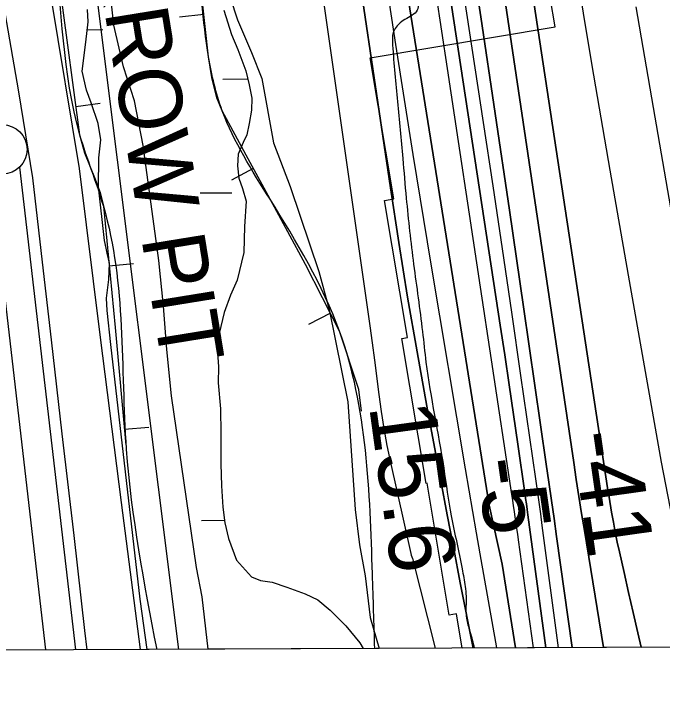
# Model space of a CAD drawing. Extents: x 3419139 to 3457078, y 540382 to 565875.
# Drawn here: x 3437926 to 3438584, y 545772 to 546482 of the extents above; entities that cross this region are included whole.
import ezdxf

# ---------------------------------------------------------------- set-up
doc = ezdxf.new("R2010")
doc.units = 0
for name, color, linetype in [('V-BORW-IDEN', 7, 'Continuous'), ('V-BORW-LINE', 7, 'Continuous'), ('V-FLOD-BASE', 7, 'Continuous'), ('V-GRID-FRAM', 7, 'Continuous'), ('V-LEVE-TOET', 7, 'Continuous'), ('V-RIVR-EDGE', 7, 'Continuous'), ('V-RIVR-RANG', 7, 'Continuous'), ('V-RRAP-RVMT', 7, 'Continuous'), ('V-SITE-VEGE', 7, 'Continuous'), ('V-SURV-LINE', 7, 'Continuous'), ('V-TOPO-DPTH', 7, 'Continuous'), ('V-TOPO-MAJR', 7, 'Continuous'), ('V-TOPO-MINR', 7, 'Continuous'), ('V-TOPO-SHOR', 7, 'Continuous'), ('V-TOPO-WATR', 7, 'Continuous'), ('V-WETL-SWMP', 7, 'Continuous')]:
    doc.layers.add(name, color=color, linetype=linetype)

msp = doc.modelspace()

# ---------------------------------------------------------------- linework, layer by layer
at = {"layer": 'V-BORW-LINE'}
for p, q in [((3438118.89, 546481.53), (3438094.04, 546478.85)), ((3437988.83, 546388.05), (3438013.6, 546391.42)), ((3438168.96, 546325.09), (3438147, 546313.15)), ((3438022.64, 546226.05), (3438047.52, 546228.45)), ((3438247.2, 546178.02), (3438224.94, 546166.63)), ((3438038.21, 546060.18), (3438063.1, 546062.48))]:
    msp.add_line(p, q, dxfattribs=at)
for points in [[(3437942.25, 546712.52), (3437948.67, 546671.17), (3437967.01, 546551.57), (3437979.67, 546455.42), (3437992.74, 546359.28), (3437997.56, 546340.87), (3438008.53, 546314.14), (3438013.51, 546300.66), (3438016.78, 546286.78), (3438028.67, 546163.44), (3438039.69, 546044.1)], [(3438278.93, 546078.47), (3438276.06, 546100.66), (3438256.5, 546159.84), (3438221.81, 546227.61), (3438185.94, 546293.87), (3438161.59, 546338.64), (3438137.5, 546383.7), (3438132.03, 546396.74), (3438126.84, 546417.38), (3438123.54, 546438.47), (3438117.54, 546494.06), (3438111.24, 546549.53), (3438101.67, 546602.31), (3438092.02, 546655.07)]]:
    msp.add_lwpolyline(points, dxfattribs=at)
for points in [[(3438092.02, 546655.07), (3438072.18, 546746.33), (3438070.57, 546844.66), (3438043.73, 546925.07), (3437954.19, 546899.65), (3437930.11, 546790.72), (3437967.01, 546551.57), (3437992.74, 546359.28), (3438016.78, 546286.78), (3438040.07, 546040.04), (3438070.94, 545836.65)], [(3438292.3, 545837.61), (3438289.94, 545913.29), (3438256.5, 546159.84), (3438185.94, 546293.87), (3438137.5, 546383.7), (3438123.54, 546438.47), (3438111.24, 546549.53), (3438092.02, 546655.07)]]:
    msp.add_spline(points, degree=3, dxfattribs=at)
at = {"layer": 'V-FLOD-BASE'}
msp.add_lwpolyline([(3437916.8, 546483.16), (3437930.62, 546402.92), (3437944.81, 546315.45), (3437955.68, 546221.11), (3437963.73, 546150.91), (3437974.68, 546055.66), (3437986.81, 545952.37), (3437997.5, 545855.97), (3438000.14, 545836.34)], dxfattribs=at)
at = {"layer": 'V-GRID-FRAM'}
msp.add_lwpolyline([(3423200.92, 563955.08), (3454837.93, 564093.12), (3454925.21, 545910.19), (3423272.32, 545772.07), (3423200.92, 563955.08)], dxfattribs=at)
at = {"layer": 'V-LEVE-TOET'}
msp.add_lwpolyline([(3437963.61, 546499.37), (3437992.25, 546324.92), (3438013.64, 546153.59), (3438034.77, 545986.02), (3438054.19, 545836.58)], dxfattribs=at)
at = {"layer": 'V-RIVR-EDGE'}
msp.add_spline([(3438029.6, 548401.43), (3438045.73, 548402.06), (3438053.4, 548398.75), (3438061.79, 548390.32), (3438061.77, 548385.2), (3438061.75, 548375.7), (3438057.34, 548366.21), (3438052.93, 548358.17), (3438050.73, 548351.97), (3438051.06, 548340.63), (3438052.5, 548331.86), (3438054.32, 548327.47), (3438053.57, 548319.42), (3438050.98, 548307.73), (3438050.59, 548295.31), (3438050.56, 548286.17), (3438052.7, 548262.77), (3438054.46, 548237.91), (3438056.96, 548212.31), (3438063.86, 548193.29), (3438064.89, 548167.69), (3438067.34, 548123.09), (3438069.47, 548097.13), (3438073.45, 548080.67), (3438079.99, 548063.84), (3438085.82, 548055.05), (3438092.37, 548044.07), (3438096.37, 548034.56), (3438099.99, 548022.48), (3438101.78, 548005.66), (3438104.97, 547964.72), (3438108.52, 547922.3), (3438110.26, 547886.47), (3438114.23, 547867.46), (3438119.66, 547845.88), (3438125.12, 547835.26), (3438137.83, 547801.23), (3438150.88, 547759.89), (3438154.82, 547724.79), (3438158.04, 547698.46), (3438169.17, 547616.55), (3438172.41, 547594.25), (3438175.3, 547583.27), (3438178.2, 547571.93), (3438178.18, 547561.33), (3438178.15, 547552.56), (3438179.97, 547548.9), (3438186.55, 547549.25), (3438192.03, 547546.31), (3438193.11, 547541.19), (3438193.1, 547535.71), (3438190.9, 547531.33), (3438186.13, 547526.95), (3438185.75, 547521.84), (3438187.21, 547518.18), (3438190.12, 547513.05), (3438190.1, 547507.2), (3438190.09, 547500.62), (3438190.08, 547497.7), (3438185.31, 547491.5), (3438184.57, 547485.65), (3438186.01, 547476.51), (3438194.33, 547443.95), (3438199.03, 547422.74), (3438199, 547408.12), (3438201.16, 547394.22), (3438204.04, 547375.57), (3438203.99, 547358.76), (3438204.3, 547334.26), (3438206.07, 547310.13), (3438210.73, 547274.66), (3438218.3, 547230.05), (3438220.47, 547219.81), (3438225.94, 547215.77), (3438232.52, 547215.76), (3438232.87, 547211.37), (3438229.94, 547206.62), (3438229.92, 547198.95), (3438232.46, 547191.63), (3438235.37, 547186.14), (3438235.36, 547182.48), (3438234.97, 547173.35), (3438233.5, 547167.5), (3438230.2, 547164.22), (3438223.61, 547162.04), (3438223.97, 547157.29), (3438226.15, 547152.17), (3438229.07, 547150.33), (3438234.92, 547151.41), (3438243.69, 547152.85), (3438248.44, 547149.19), (3438249.88, 547140.04), (3438251.3, 547125.78), (3438250.55, 547117.01), (3438245.78, 547109.71), (3438239.19, 547106.81), (3438225.66, 547102.09), (3438222.36, 547099.17), (3438219.42, 547093.7), (3438217.2, 547082.73), (3438216.8, 547067.75), (3438218.96, 547055.68), (3438228.8, 547041.03), (3438234.26, 547034.81), (3438234.24, 547026.76), (3438234.23, 547019.82), (3438234.58, 547013.97), (3438237.12, 547005.55), (3438239.28, 546994.58), (3438242.56, 546990.92), (3438247.68, 546989.44), (3438253.51, 546981.75), (3438257.5, 546969.31), (3438259.67, 546959.44), (3438258.9, 546944.09), (3438254.86, 546937.52), (3438253.38, 546932.04), (3438253.37, 546924.73), (3438259.2, 546918.86), (3438262.47, 546912.28), (3438266.09, 546895.82), (3438272.63, 546878.99), (3438274.42, 546864.73), (3438272.92, 546851.2), (3438272.17, 546840.24), (3438274.72, 546839.87), (3438276.2, 546844.25), (3438280.23, 546850.45), (3438283.52, 546849.72), (3438283.88, 546845.33), (3438283.85, 546832.9), (3438282.36, 546823.4), (3438276.86, 546817.56), (3438271, 546811.36), (3438270.99, 546807.71), (3438272.79, 546798.57), (3438280.81, 546788.31), (3438282.27, 546788.67), (3438287.77, 546791.95), (3438291.78, 546790.11), (3438292.5, 546784.26), (3438292.13, 546781.34), (3438288.46, 546778.79), (3438285.53, 546773.68), (3438283.32, 546766.74), (3438282.92, 546755.41), (3438281.8, 546746.64), (3438286.87, 546723.96), (3438290.44, 546690.68), (3438295.81, 546645.34), (3438301.55, 546600), (3438307.65, 546556.49), (3438313.8, 546530.88), (3438318.89, 546519.54), (3438322.18, 546516.97), (3438327.66, 546516.96), (3438334.96, 546511.09), (3438335.65, 546496.47), (3438336, 546487.33), (3438324.64, 546477.49), (3438318.05, 546473.12), (3438311.08, 546463.26), (3438310.32, 546450.47), (3438315.29, 546393.07), (3438320.63, 546335.3), (3438324.19, 546295.08), (3438331.7, 546227.8), (3438340.67, 546159.42), (3438344.25, 546128.34), (3438362.26, 546020.82), (3438369.81, 545972.19), (3438381.01, 545918.42), (3438383.89, 545900.5), (3438384.97, 545890.63), (3438384.95, 545884.42), (3438385.28, 545868.33), (3438388.9, 545854.8), (3438393.3, 545838.05)], degree=3, dxfattribs=at)
at = {"layer": 'V-RRAP-RVMT'}
for p, q in [((3438475.22, 546468.82), (3438451.09, 546613.22)), ((3438287.6, 546437.47), (3438475.22, 546468.82)), ((3438311.45, 546294.18), (3438287.6, 546437.47)), ((3438302.11, 546292.65), (3438311.45, 546294.18)), ((3438325.37, 546153.31), (3438302.11, 546292.65)), ((3438319.77, 546152.4), (3438325.37, 546153.31)), ((3438344.37, 546005.18), (3438319.77, 546152.4)), ((3438345.57, 546005.37), (3438344.37, 546005.18)), ((3438367.93, 545871.53), (3438345.57, 546005.37)), ((3438375.24, 545872.72), (3438367.93, 545871.53)), ((3438381.03, 545838), (3438375.24, 545872.72)), ((3438730.73, 545839.53), (3438381.03, 545838))]:
    msp.add_line(p, q, dxfattribs=at)
at = {"layer": 'V-SITE-VEGE'}
for p, q in [((3438027.33, 546470.7), (3438023.42, 546508.36)), ((3438144.7, 546501.48), (3438152.97, 546476.18)), ((3438152.97, 546476.18), (3438167.04, 546442.93)), ((3438037.4, 546428.38), (3438027.33, 546470.7)), ((3438167.04, 546442.93), (3438177.72, 546416.41)), ((3438048.37, 546393.77), (3438037.4, 546428.38)), ((3438177.72, 546416.41), (3438189.55, 546351.04)), ((3438057.04, 546348.53), (3438048.37, 546393.77)), ((3438073.22, 546231.76), (3438057.04, 546348.53)), ((3438189.55, 546351.04), (3438206.31, 546306.61)), ((3438206.31, 546306.61), (3438216.45, 546276.65)), ((3438216.45, 546276.65), (3438235.54, 546220.53)), ((3438077.77, 546185.16), (3438073.22, 546231.76)), ((3438235.54, 546220.53), (3438245.81, 546181.8)), ((3438081.3, 546141.32), (3438077.77, 546185.16)), ((3438245.81, 546181.8), (3438264.86, 546088.04)), ((3438086.01, 546094.04), (3438081.3, 546141.32)), ((3438111.31, 545919.82), (3438086.01, 546094.04)), ((3438264.86, 546088.04), (3438272.32, 545978.71)), ((3438272.32, 545978.71), (3438276.75, 545942.94)), ((3438276.75, 545942.94), (3438282.59, 545911.46)), ((3438116.98, 545890.06), (3438111.31, 545919.82)), ((3438282.59, 545911.46), (3438287.5, 545869.16)), ((3438123.02, 545836.88), (3438116.98, 545890.06)), ((3438287.5, 545869.16), (3438296.67, 545837.63)), ((3438296.67, 545837.63), (3438123.02, 545836.88))]:
    msp.add_line(p, q, dxfattribs=at)
at = {"layer": 'V-SURV-LINE'}
for points in [[(3437958.31, 545836.16), (3437901.77, 546322.87)], [(3437931.57, 546326.35), (3437988.49, 545836.29)]]:
    msp.add_lwpolyline(points, dxfattribs=at)
msp.add_circle((3437914.36, 546344.46), 25, dxfattribs=at)
at = {"layer": 'V-TOPO-DPTH'}
for points in [[(3437991.54, 548933.35), (3438051.83, 548524.53), (3438060.22, 548473.42), (3438165.61, 547710.29), (3438237.41, 547136.26), (3438265.79, 546904.61), (3438321.05, 546529.85), (3438408.25, 545983.03), (3438421.72, 545923.4), (3438435.06, 545838.24)], [(3437991.54, 548933.35), (3438051.83, 548524.53), (3438060.22, 548473.42), (3438165.61, 547710.29), (3438237.41, 547136.26), (3438265.79, 546904.61), (3438321.05, 546529.85), (3438408.25, 545983.03), (3438421.72, 545923.4), (3438435.06, 545838.24)], [(3438243.53, 547691.29), (3438244.92, 547681.67), (3438246.33, 547672.05), (3438247.76, 547662.43), (3438249.21, 547652.81), (3438357, 546943.52), (3438359.01, 546930.3), (3438361.02, 546917.08), (3438363.04, 546903.86), (3438365.05, 546890.64), (3438380.95, 546786.36), (3438390.87, 546720.99), (3438400.74, 546655.62), (3438410.53, 546590.24), (3438420.27, 546524.84), (3438494.14, 546026.61), (3438496.76, 546009.27), (3438499.42, 545991.94), (3438502.17, 545974.61), (3438504.97, 545957.3), (3438524.44, 545838.63)], [(3438524.44, 545838.63), (3438504.97, 545957.3), (3438502.17, 545974.61), (3438499.42, 545991.94), (3438496.76, 546009.27), (3438494.14, 546026.61), (3438420.27, 546524.84), (3438410.53, 546590.24), (3438400.74, 546655.62), (3438390.87, 546720.99), (3438380.95, 546786.36), (3438365.05, 546890.64), (3438363.04, 546903.86), (3438361.02, 546917.08), (3438359.01, 546930.3), (3438357, 546943.52), (3438249.21, 547652.81), (3438247.76, 547662.43), (3438246.33, 547672.05), (3438244.92, 547681.67), (3438243.53, 547691.29)], [(3438220.75, 547679.15), (3438239.4, 547547.91), (3438250.77, 547468.62), (3438262.28, 547389.35), (3438274, 547310.11), (3438285.84, 547230.89), (3438325.78, 546966.16), (3438329.83, 546939.32), (3438333.89, 546912.49), (3438337.96, 546885.66), (3438342.04, 546858.83), (3438384.92, 546577.27), (3438399.75, 546479.12), (3438414.44, 546380.95), (3438428.91, 546282.75), (3438443.23, 546184.53), (3438466.36, 546024.71), (3438469, 546006.38), (3438471.63, 545988.05), (3438474.23, 545969.72), (3438476.83, 545951.38), (3438492.71, 545838.49)], [(3438492.71, 545838.49), (3438476.83, 545951.38), (3438474.23, 545969.72), (3438471.63, 545988.05), (3438469, 546006.38), (3438466.36, 546024.71), (3438443.23, 546184.53), (3438428.91, 546282.75), (3438414.44, 546380.95), (3438399.75, 546479.12), (3438384.92, 546577.27), (3438342.04, 546858.83), (3438337.96, 546885.66), (3438333.89, 546912.49), (3438329.83, 546939.32), (3438325.78, 546966.16), (3438285.84, 547230.89), (3438274, 547310.11), (3438262.28, 547389.35), (3438250.77, 547468.62), (3438239.4, 547547.91), (3438220.75, 547679.15)], [(3438465.78, 545838.37), (3438447.66, 545973.31), (3438446.9, 545978.9), (3438446.13, 545984.49), (3438445.35, 545990.07), (3438444.56, 545995.66), (3438437.47, 546045), (3438433.08, 546075.25), (3438428.65, 546105.5), (3438424.14, 546135.73), (3438419.58, 546165.96), (3438319.04, 546827.04), (3438312.9, 546867.47), (3438306.79, 546907.91), (3438300.7, 546948.35), (3438294.63, 546988.8), (3438292.35, 547004.01), (3438285.22, 547052.08), (3438278.17, 547100.15), (3438271.23, 547148.24), (3438264.38, 547196.35), (3438200.19, 547651.1)], [(3438465.78, 545838.37), (3438447.66, 545973.31), (3438446.9, 545978.9), (3438446.13, 545984.49), (3438445.35, 545990.07), (3438444.56, 545995.66), (3438437.47, 546045), (3438433.08, 546075.25), (3438428.65, 546105.5), (3438424.14, 546135.73), (3438419.58, 546165.96), (3438319.04, 546827.04), (3438312.9, 546867.47), (3438306.79, 546907.91), (3438300.7, 546948.35), (3438294.63, 546988.8), (3438292.35, 547004.01), (3438285.22, 547052.08), (3438278.17, 547100.15), (3438271.23, 547148.24), (3438264.38, 547196.35), (3438200.19, 547651.1)], [(3438392.08, 545838.05), (3438379.05, 545904.41), (3438372.35, 545938.83), (3438365.72, 545973.26), (3438359.21, 546007.71), (3438352.77, 546042.18), (3438345.07, 546083.73), (3438335.14, 546139.04), (3438325.6, 546194.41), (3438316.67, 546249.88), (3438308.15, 546305.42), (3438231.16, 546825.55), (3438226.28, 546859.51), (3438221.57, 546893.5), (3438217.14, 546927.52), (3438212.88, 546961.56), (3438182.8, 547210.53), (3438173.19, 547290.63), (3438163.65, 547370.74), (3438154.24, 547450.87), (3438144.91, 547531), (3438135.63, 547611.22)], [(3438431.54, 546639.16), (3438528.55, 546000.86), (3438528.91, 545998.48), (3438529.68, 545993.74), (3438530.07, 545991.36), (3438532.69, 545975.89), (3438534.48, 545965.8), (3438536.38, 545955.73), (3438538.44, 545945.69), (3438540.6, 545935.67), (3438545.28, 545914.82), (3438549.89, 545894.41), (3438554.55, 545874), (3438559.27, 545853.61), (3438562.72, 545838.79)], [(3438431.54, 546639.16), (3438528.55, 546000.86), (3438528.91, 545998.48), (3438529.68, 545993.74), (3438530.07, 545991.36), (3438532.69, 545975.89), (3438534.48, 545965.8), (3438536.38, 545955.73), (3438538.44, 545945.69), (3438540.6, 545935.67), (3438545.28, 545914.82), (3438549.89, 545894.41), (3438554.55, 545874), (3438559.27, 545853.61), (3438562.72, 545838.79), (3440821.37, 545848.65)]]:
    msp.add_lwpolyline(points, dxfattribs=at)
at = {"layer": 'V-TOPO-MAJR'}
msp.add_lwpolyline([(3438621.22, 545839.05), (3438617.83, 545855.71), (3438596.6, 545958.95), (3438592.04, 545981.6), (3438587.6, 546004.27), (3438583.35, 546026.98), (3438579.23, 546049.72), (3438549.62, 546216.89), (3438531.06, 546323.27), (3438512.86, 546429.71), (3438495.22, 546536.25), (3438477.95, 546642.85), (3438439.49, 546884.12), (3438435.9, 546906.62), (3438432.31, 546929.12), (3438428.7, 546951.61), (3438425.1, 546974.11), (3438392.06, 547179.92), (3438377.72, 547270.2), (3438363.58, 547360.5), (3438349.74, 547450.86), (3438336.1, 547541.24), (3438314.15, 547688.35)], dxfattribs=at)
at = {"layer": 'V-TOPO-MINR'}
for points in [[(3438243.53, 547691.29), (3438244.92, 547681.67), (3438246.33, 547672.05), (3438247.76, 547662.43), (3438249.21, 547652.81), (3438357, 546943.52), (3438359.01, 546930.3), (3438361.02, 546917.08), (3438363.04, 546903.86), (3438365.05, 546890.64), (3438380.95, 546786.36), (3438390.87, 546720.99), (3438400.74, 546655.62), (3438410.53, 546590.24), (3438420.27, 546524.84), (3438494.14, 546026.61), (3438496.76, 546009.27), (3438499.42, 545991.94), (3438502.17, 545974.61), (3438504.97, 545957.3), (3438524.44, 545838.63)], [(3438220.75, 547679.15), (3438239.4, 547547.91), (3438250.77, 547468.62), (3438262.28, 547389.35), (3438274, 547310.11), (3438285.84, 547230.89), (3438325.78, 546966.16), (3438329.83, 546939.32), (3438333.89, 546912.49), (3438337.96, 546885.66), (3438342.04, 546858.83), (3438384.92, 546577.27), (3438399.75, 546479.12), (3438414.44, 546380.95), (3438428.91, 546282.75), (3438443.23, 546184.53), (3438466.36, 546024.71), (3438469, 546006.38), (3438471.63, 545988.05), (3438474.23, 545969.72), (3438476.83, 545951.38), (3438492.71, 545838.49)], [(3438210.48, 547665.12), (3438246.13, 547413.41), (3438258.13, 547329.49), (3438270.26, 547245.59), (3438282.61, 547161.72), (3438295.11, 547077.87), (3438310.19, 546977.48), (3438315.26, 546943.84), (3438320.34, 546910.2), (3438325.43, 546876.57), (3438330.54, 546842.93), (3438402.24, 546371.8), (3438411.93, 546307.58), (3438421.52, 546243.35), (3438430.94, 546179.09), (3438440.26, 546114.82), (3438455.33, 546009.99), (3438457.02, 545998.12), (3438458.68, 545986.24), (3438460.3, 545974.36), (3438461.89, 545962.47), (3438478.34, 545838.43)], [(3438200.19, 547651.1), (3438264.38, 547196.35), (3438271.23, 547148.24), (3438278.17, 547100.15), (3438285.22, 547052.08), (3438292.35, 547004.01), (3438294.63, 546988.8), (3438300.7, 546948.35), (3438306.79, 546907.91), (3438312.9, 546867.47), (3438319.04, 546827.04), (3438419.58, 546165.96), (3438424.14, 546135.73), (3438428.65, 546105.5), (3438433.08, 546075.25), (3438437.47, 546045), (3438444.56, 545995.66), (3438445.35, 545990.07), (3438446.13, 545984.49), (3438446.9, 545978.9), (3438447.66, 545973.31), (3438465.78, 545838.37)], [(3438096.72, 547640.47), (3438166.56, 547036.4), (3438169.46, 547011.53), (3438172.38, 546986.66), (3438175.34, 546961.8), (3438178.32, 546936.94), (3438183.62, 546893.11), (3438183.98, 546890.17), (3438184.36, 546887.22), (3438184.76, 546884.28), (3438185.16, 546881.34), (3438287.26, 546165.36), (3438289.67, 546147.97), (3438292, 546130.56), (3438296.32, 546095.71), (3438298.64, 546078.31), (3438301.32, 546060.98), (3438304.53, 546043.73), (3438308.09, 546026.55), (3438328.72, 545934.23), (3438329.2, 545932.49), (3438330.53, 545929.15), (3438353.42, 545837.88)], [(3438135.63, 547611.22), (3438144.91, 547531), (3438154.24, 547450.87), (3438163.65, 547370.74), (3438173.19, 547290.63), (3438182.8, 547210.53), (3438212.88, 546961.56), (3438217.14, 546927.52), (3438221.57, 546893.5), (3438226.28, 546859.51), (3438231.16, 546825.55), (3438308.15, 546305.42), (3438316.67, 546249.88), (3438325.6, 546194.41), (3438335.14, 546139.04), (3438345.07, 546083.73), (3438352.77, 546042.18), (3438359.21, 546007.71), (3438365.72, 545973.26), (3438372.35, 545938.83), (3438379.05, 545904.41), (3438392.08, 545838.05)], [(3438164.93, 547597.13), (3438169.01, 547564.27), (3438173.02, 547531.4), (3438176.98, 547498.52), (3438243.81, 546938.52), (3438246.28, 546918.31), (3438248.85, 546898.11), (3438251.54, 546877.94), (3438254.31, 546857.77), (3438280.15, 546674.38), (3438296.36, 546562.59), (3438313.17, 546450.9), (3438330.88, 546339.34), (3438349.19, 546227.88), (3438384.17, 546020.18), (3438387.84, 545998.52), (3438391.54, 545976.86), (3438395.28, 545955.21), (3438399.05, 545933.57), (3438415.75, 545838.15)], [(3438296.76, 546881.95), (3438365.7, 546426.59), (3438376.9, 546352.6), (3438388.1, 546278.6), (3438399.3, 546204.61), (3438410.49, 546130.62), (3438431.15, 545994.15), (3438432.01, 545988.39), (3438432.87, 545982.63), (3438433.7, 545976.87), (3438434.53, 545971.11), (3438435.35, 545965.35), (3438436.17, 545959.58), (3438436.97, 545953.82), (3438437.78, 545948.05), (3438453, 545838.32)], [(3438562.72, 545838.79), (3438559.27, 545853.61), (3438554.55, 545874), (3438549.89, 545894.41), (3438545.28, 545914.82), (3438540.6, 545935.67), (3438538.44, 545945.69), (3438536.38, 545955.73), (3438534.48, 545965.8), (3438532.69, 545975.89), (3438530.07, 545991.36), (3438529.68, 545993.74), (3438528.91, 545998.48), (3438528.55, 546000.86), (3438431.54, 546639.16)], [(3438557.37, 546489.15), (3438574.89, 546387.12), (3438592.47, 546285.11), (3438625.33, 546095.12), (3438627.79, 546081.19), (3438630.32, 546067.28), (3438632.96, 546053.38), (3438635.66, 546039.49), (3438638.43, 546025.62), (3438641.25, 546011.76), (3438644.11, 545997.91), (3438647.01, 545984.06), (3438677.63, 545839.3)]]:
    msp.add_lwpolyline(points, dxfattribs=at)
at = {"layer": 'V-TOPO-SHOR'}
msp.add_line((3438093.43, 545836.75), (3437956.66, 546928.86), dxfattribs=at)
at = {"layer": 'V-TOPO-WATR'}
msp.add_lwpolyline([(3438435.06, 545838.24), (3438421.72, 545923.4), (3438408.25, 545983.03), (3438321.05, 546529.85), (3438265.79, 546904.61), (3438237.41, 547136.26), (3438165.61, 547710.29), (3438060.22, 548473.42), (3438051.83, 548524.53), (3437991.54, 548933.35)], dxfattribs=at)
at = {"layer": 'V-WETL-SWMP'}
for p, q in [((3438001.34, 546474.14), (3438000.7, 546486.6)), ((3438139.14, 546485.82), (3438146.83, 546461.21)), ((3437999.08, 546453.51), (3438001.34, 546474.14)), ((3438000.45, 546466.02), (3438016.4, 546466.09)), ((3438146.83, 546461.21), (3438153.15, 546445.87)), ((3437995.36, 546424), (3437999.08, 546453.51)), ((3438153.15, 546445.87), (3438161.56, 546424.12)), ((3437999.52, 546404.75), (3437995.36, 546424)), ((3438161.56, 546424.12), (3438164.68, 546409.86)), ((3438137.93, 546415.88), (3438163.34, 546415.99)), ((3438004.43, 546391.91), (3437999.52, 546404.75)), ((3438164.68, 546409.86), (3438167.45, 546396.32)), ((3438011.43, 546370.88), (3438004.43, 546391.91)), ((3438167.45, 546396.32), (3438167.03, 546384.23)), ((3438167.03, 546384.23), (3438164.82, 546370.71)), ((3438014.18, 546354.13), (3438011.43, 546370.88)), ((3438164.82, 546370.71), (3438162.26, 546359.34)), ((3438162.26, 546359.34), (3438158.66, 546351.53)), ((3438012.29, 546335.99), (3438014.18, 546354.13)), ((3438158.66, 546351.53), (3438153.61, 546339.46)), ((3438011.77, 546306.46), (3438012.29, 546335.99)), ((3438153.61, 546339.46), (3438152.83, 546327.72)), ((3438152.83, 546327.72), (3438154.18, 546315.25)), ((3438154.18, 546315.25), (3438158.04, 546304.91)), ((3438017.87, 546251.97), (3438011.77, 546306.46)), ((3438115.03, 546300.34), (3438147.03, 546300.48)), ((3438158.04, 546304.91), (3438161.88, 546291.72)), ((3438161.88, 546291.72), (3438159.95, 546266.11)), ((3438159.95, 546266.11), (3438159.45, 546239.77)), ((3438019.6, 546244.13), (3438017.87, 546251.97)), ((3438020.64, 546239.14), (3438019.6, 546244.13)), ((3438023.07, 546228.81), (3438020.64, 546239.14)), ((3438159.45, 546239.77), (3438152.52, 546211.7)), ((3438022.27, 546212.44), (3438023.07, 546228.81)), ((3438020.02, 546193.23), (3438022.27, 546212.44)), ((3438152.52, 546211.7), (3438145.67, 546196.43)), ((3438020.66, 546180.77), (3438020.02, 546193.23)), ((3438145.67, 546196.43), (3438139.52, 546178.67)), ((3438024.38, 546146.23), (3438020.66, 546180.77)), ((3438139.52, 546178.67), (3438134.42, 546157.35)), ((3438134.42, 546157.35), (3438132.53, 546138.14)), ((3438054.23, 545887.68), (3438024.38, 546146.23)), ((3438132.53, 546138.14), (3438133.51, 546123.54)), ((3438133.51, 546123.54), (3438133.42, 546107.53)), ((3438133.42, 546107.53), (3438135.76, 546080.82)), ((3438135.76, 546080.82), (3438135.98, 546055.91)), ((3438135.98, 546055.91), (3438136.16, 546025.3)), ((3438136.16, 546025.3), (3438136.74, 546002.87)), ((3438136.74, 546002.87), (3438138.04, 545981.16)), ((3438138.04, 545981.16), (3438140.09, 545965.13)), ((3438116.48, 545967.67), (3438139.75, 545967.77)), ((3438140.09, 545965.13), (3438143.91, 545949.45)), ((3438143.91, 545949.45), (3438151.97, 545927.34)), ((3438151.97, 545927.34), (3438167.18, 545910.52)), ((3438167.18, 545910.52), (3438176.41, 545906.56)), ((3438176.41, 545906.56), (3438188.15, 545905.06)), ((3438188.15, 545905.06), (3438203.06, 545900)), ((3438203.06, 545900), (3438221.53, 545893.13)), ((3438061.17, 545836.61), (3438054.23, 545887.68)), ((3438221.53, 545893.13), (3438234.31, 545887.01)), ((3438234.31, 545887.01), (3438247.06, 545876.61)), ((3438247.06, 545876.61), (3438262.99, 545860.51)), ((3438262.99, 545860.51), (3438277.13, 545843.34)), ((3438280.55, 545837.56), (3438061.17, 545836.61)), ((3438277.13, 545843.34), (3438280.55, 545837.56))]:
    msp.add_line(p, q, dxfattribs=at)

# ---------------------------------------------------------------- texts
at = {"layer": 'V-BORW-IDEN'}
msp.add_text('BORROW PIT', height=64, rotation=279.21967, dxfattribs=at).set_placement((3437988.21, 546667.44))
at = {"layer": 'V-RIVR-RANG'}
for s, rotation, p in [('15.6', 277.80833, (3438286.38, 546083.97)), ('-41', 278.09633, (3438491.79, 546055.77)), ('-5', 278.09633, (3438394.65, 546028.61))]:
    msp.add_text(s, height=67, rotation=rotation, dxfattribs=at).set_placement(p)

doc.saveas('drawing.dxf')
